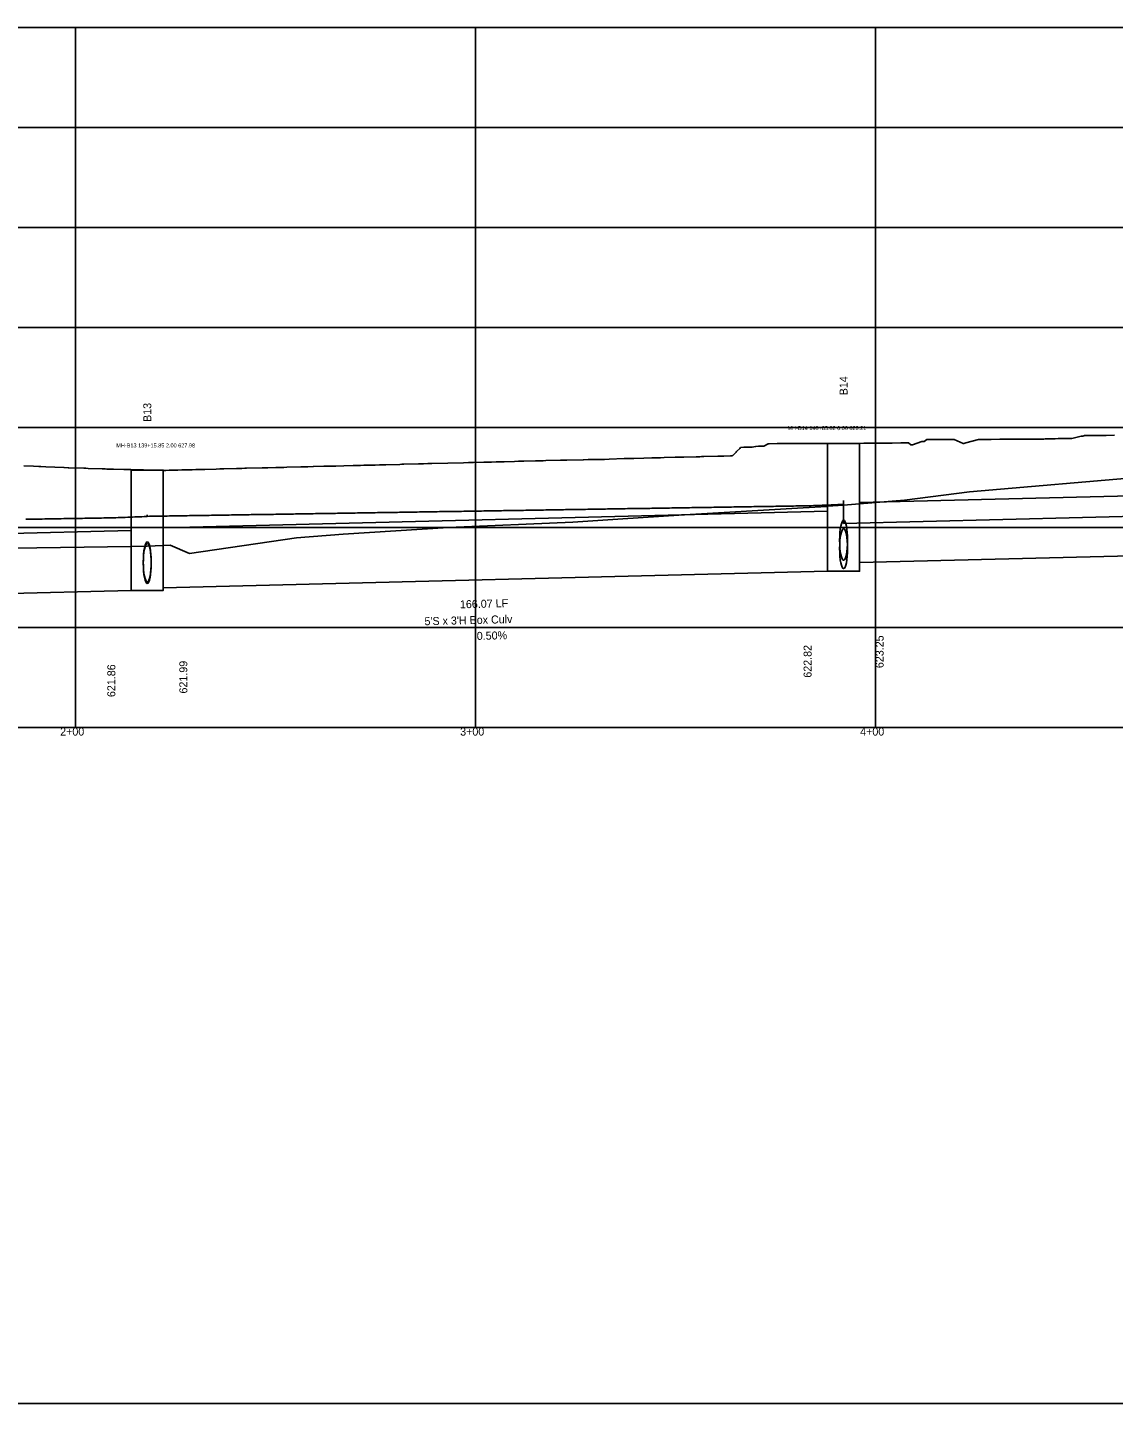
# Model space of a CAD drawing. Extents: x 2253035 to 2279930, y 13774972 to 13793443.
# Drawn here: x 2260149.5 to 2260421, y 13791972.5 to 13792316.4 of the extents above; entities that cross this region are included whole.
import ezdxf

# ---------------------------------------------------------------- set-up
doc = ezdxf.new("R2010")
doc.units = 0
for name, color, linetype in [('Default', 7, 'Continuous'), ('E_Utility_ATT_HH', 7, 'Continuous'), ('E_Utility_ATT_PR_PVC', 7, 'Continuous'), ('E_Utility_Telephone_Telephone Pedestal_TPED_Description', 7, 'Continuous'), ('E_Utillity_Water_Water Line_12in', 7, 'Continuous'), ('E_Utillity_Water_Water Line_1in', 7, 'Continuous'), ('E_Utillity_Water_Water Line_4in', 7, 'Continuous'), ('E_Utillity_Water_Water Line_8in', 7, 'Continuous')]:
    doc.layers.add(name, color=color, linetype=linetype)

msp = doc.modelspace()

# ---------------------------------------------------------------- linework, layer by layer
at = {"layer": 'Default'}
for p, q in [((2260161.48, 13792141.44), (2260161.48, 13792316.44)), ((2260261.48, 13792141.44), (2260261.48, 13792316.44)), ((2260361.48, 13792141.44), (2260361.48, 13792316.44)), ((2259961.48, 13792291.44), (2261350.66, 13792291.44)), ((2259961.48, 13792266.44), (2261350.66, 13792266.44)), ((2259961.48, 13792241.44), (2261350.66, 13792241.44)), ((2259961.48, 13792216.44), (2261350.66, 13792216.44)), ((2259961.48, 13792191.44), (2261350.66, 13792191.44)), ((2259961.48, 13792166.44), (2261350.66, 13792166.44)), ((2258357.4, 13791972.48), (2265626.63, 13791972.48))]:
    msp.add_line(p, q, dxfattribs=at)
msp.add_lwpolyline([(2259961.48, 13792141.44), (2259961.48, 13792316.44), (2261350.66, 13792316.44), (2261350.66, 13792141.44)], close=True, dxfattribs=at)
at = {"layer": 'E_Utility_ATT_PR_PVC'}
for p, q in [((2260353.54, 13792198.25), (2260353.54, 13792192.44)), ((2260179.47, 13792194.65), (2260179.47, 13792194.25))]:
    msp.add_line(p, q, dxfattribs=at)
for points in [[(2260179.47, 13792194.25), (2260180.02, 13792194.26), (2260180.57, 13792194.27), (2260181.13, 13792194.28), (2260181.68, 13792194.29), (2260182.23, 13792194.29), (2260182.79, 13792194.3), (2260183.34, 13792194.31), (2260183.89, 13792194.32), (2260184.45, 13792194.33), (2260185, 13792194.34), (2260185.55, 13792194.35), (2260186.11, 13792194.36), (2260186.66, 13792194.36), (2260187.21, 13792194.37), (2260187.77, 13792194.38), (2260188.32, 13792194.39), (2260188.87, 13792194.4), (2260189.43, 13792194.41), (2260189.98, 13792194.42), (2260190.53, 13792194.43), (2260191.08, 13792194.44), (2260191.64, 13792194.44), (2260192.19, 13792194.45), (2260192.74, 13792194.46), (2260193.3, 13792194.47), (2260193.85, 13792194.48), (2260194.4, 13792194.49), (2260194.96, 13792194.5), (2260195.51, 13792194.51), (2260196.06, 13792194.51), (2260196.62, 13792194.52), (2260197.17, 13792194.53), (2260197.72, 13792194.54), (2260198.28, 13792194.55), (2260198.83, 13792194.56), (2260199.38, 13792194.57), (2260199.94, 13792194.58), (2260200.49, 13792194.59), (2260201.04, 13792194.59), (2260201.6, 13792194.6), (2260202.15, 13792194.61), (2260202.7, 13792194.62), (2260203.26, 13792194.63), (2260203.81, 13792194.64), (2260204.36, 13792194.65), (2260204.92, 13792194.66), (2260205.47, 13792194.67), (2260206.02, 13792194.67), (2260206.58, 13792194.68), (2260207.13, 13792194.69), (2260207.68, 13792194.7), (2260208.24, 13792194.71), (2260208.79, 13792194.72), (2260209.34, 13792194.73), (2260209.9, 13792194.74), (2260210.45, 13792194.74), (2260211, 13792194.75), (2260211.56, 13792194.76), (2260212.11, 13792194.77), (2260212.66, 13792194.78), (2260213.22, 13792194.79), (2260213.77, 13792194.8), (2260214.32, 13792194.81), (2260214.88, 13792194.82), (2260215.43, 13792194.82), (2260215.98, 13792194.83), (2260216.54, 13792194.84), (2260217.09, 13792194.85), (2260217.64, 13792194.86), (2260218.2, 13792194.87), (2260218.75, 13792194.88), (2260219.3, 13792194.89), (2260219.86, 13792194.89), (2260220.41, 13792194.9), (2260220.96, 13792194.91), (2260221.51, 13792194.92), (2260222.07, 13792194.93), (2260222.62, 13792194.94), (2260223.17, 13792194.95), (2260223.73, 13792194.96), (2260224.28, 13792194.97), (2260224.83, 13792194.97), (2260225.39, 13792194.98), (2260225.94, 13792194.99), (2260226.49, 13792195), (2260227.05, 13792195.01), (2260227.6, 13792195.02), (2260228.15, 13792195.03), (2260228.71, 13792195.04), (2260229.26, 13792195.04), (2260229.81, 13792195.05), (2260230.37, 13792195.06), (2260230.92, 13792195.07), (2260231.47, 13792195.08), (2260232.03, 13792195.09), (2260232.58, 13792195.1), (2260233.13, 13792195.11), (2260233.69, 13792195.12), (2260234.24, 13792195.12), (2260234.79, 13792195.13), (2260235.35, 13792195.14), (2260235.9, 13792195.15), (2260236.45, 13792195.16), (2260237.01, 13792195.17), (2260237.56, 13792195.18), (2260238.11, 13792195.19), (2260238.67, 13792195.19), (2260239.22, 13792195.2), (2260239.77, 13792195.21), (2260240.33, 13792195.22), (2260240.88, 13792195.23), (2260241.43, 13792195.24), (2260241.99, 13792195.25), (2260242.54, 13792195.26), (2260243.09, 13792195.27), (2260243.65, 13792195.27), (2260244.2, 13792195.28), (2260244.75, 13792195.29), (2260245.31, 13792195.3), (2260245.86, 13792195.31), (2260246.41, 13792195.32), (2260246.97, 13792195.33), (2260247.52, 13792195.34), (2260248.07, 13792195.35), (2260248.63, 13792195.35), (2260249.18, 13792195.36), (2260249.73, 13792195.37), (2260250.29, 13792195.38), (2260250.84, 13792195.39), (2260251.39, 13792195.4), (2260251.94, 13792195.41), (2260252.5, 13792195.42), (2260253.05, 13792195.42), (2260253.6, 13792195.43), (2260254.16, 13792195.44), (2260254.71, 13792195.45), (2260255.26, 13792195.46), (2260255.82, 13792195.47), (2260256.37, 13792195.48), (2260256.92, 13792195.49), (2260257.48, 13792195.5), (2260258.03, 13792195.5), (2260258.58, 13792195.51), (2260259.14, 13792195.52), (2260259.69, 13792195.53), (2260260.24, 13792195.54), (2260260.8, 13792195.55), (2260261.35, 13792195.56), (2260261.9, 13792195.57), (2260262.46, 13792195.57), (2260263.01, 13792195.58), (2260263.56, 13792195.59), (2260264.12, 13792195.6), (2260264.67, 13792195.61), (2260265.22, 13792195.62), (2260265.78, 13792195.63), (2260266.33, 13792195.64), (2260266.88, 13792195.65), (2260267.44, 13792195.65), (2260267.99, 13792195.66), (2260268.54, 13792195.67), (2260269.1, 13792195.68), (2260269.65, 13792195.69), (2260270.2, 13792195.7), (2260270.76, 13792195.71), (2260271.31, 13792195.72), (2260271.86, 13792195.72), (2260272.42, 13792195.73), (2260272.97, 13792195.74), (2260273.52, 13792195.75), (2260274.08, 13792195.76), (2260274.63, 13792195.77), (2260275.18, 13792195.78), (2260275.74, 13792195.79), (2260276.29, 13792195.8), (2260276.84, 13792195.8), (2260277.4, 13792195.81), (2260277.95, 13792195.82), (2260278.5, 13792195.83), (2260279.06, 13792195.84), (2260279.61, 13792195.85), (2260280.16, 13792195.86), (2260280.72, 13792195.87), (2260281.27, 13792195.87), (2260281.82, 13792195.88), (2260282.37, 13792195.89), (2260282.93, 13792195.9), (2260283.48, 13792195.91), (2260284.03, 13792195.92), (2260284.59, 13792195.93), (2260285.14, 13792195.94), (2260285.69, 13792195.95), (2260286.25, 13792195.95), (2260286.8, 13792195.96), (2260287.35, 13792195.97), (2260287.91, 13792195.98), (2260288.46, 13792195.99), (2260289.01, 13792196), (2260289.57, 13792196.01), (2260290.12, 13792196.02), (2260290.67, 13792196.03), (2260291.23, 13792196.03), (2260291.78, 13792196.04), (2260292.33, 13792196.05), (2260292.89, 13792196.06), (2260293.44, 13792196.07), (2260293.99, 13792196.08), (2260294.55, 13792196.09), (2260295.1, 13792196.1), (2260295.65, 13792196.1), (2260296.21, 13792196.11), (2260296.76, 13792196.12), (2260297.31, 13792196.13), (2260297.87, 13792196.14), (2260298.42, 13792196.15), (2260298.97, 13792196.16), (2260299.53, 13792196.17), (2260300.08, 13792196.18), (2260300.63, 13792196.18), (2260301.19, 13792196.19), (2260301.74, 13792196.2), (2260302.29, 13792196.21), (2260302.85, 13792196.22), (2260303.4, 13792196.23), (2260303.95, 13792196.24), (2260304.51, 13792196.25), (2260305.06, 13792196.25), (2260305.61, 13792196.26), (2260306.17, 13792196.27), (2260306.72, 13792196.28), (2260307.27, 13792196.29), (2260307.83, 13792196.3), (2260308.38, 13792196.31), (2260308.93, 13792196.32), (2260309.49, 13792196.33), (2260310.04, 13792196.33), (2260310.59, 13792196.34), (2260311.15, 13792196.35), (2260311.7, 13792196.36), (2260312.25, 13792196.37), (2260312.8, 13792196.38), (2260313.36, 13792196.39), (2260313.91, 13792196.4), (2260314.46, 13792196.4), (2260315.02, 13792196.41), (2260315.57, 13792196.42), (2260316.12, 13792196.43), (2260316.68, 13792196.44), (2260317.23, 13792196.45), (2260317.78, 13792196.46), (2260318.34, 13792196.47), (2260318.89, 13792196.48), (2260319.44, 13792196.48), (2260320, 13792196.49), (2260320.55, 13792196.5), (2260321.1, 13792196.51), (2260321.66, 13792196.52), (2260322.21, 13792196.53), (2260322.76, 13792196.54), (2260323.32, 13792196.55), (2260323.87, 13792196.56), (2260324.42, 13792196.56), (2260324.98, 13792196.57), (2260325.53, 13792196.58), (2260326.08, 13792196.59), (2260326.64, 13792196.6), (2260327.19, 13792196.61), (2260327.74, 13792196.62), (2260328.3, 13792196.63), (2260328.85, 13792196.63), (2260329.4, 13792196.64), (2260329.96, 13792196.65), (2260330.51, 13792196.66), (2260331.06, 13792196.67), (2260331.62, 13792196.68), (2260332.17, 13792196.69), (2260332.72, 13792196.7), (2260333.28, 13792196.71), (2260333.83, 13792196.71), (2260334.38, 13792196.72), (2260334.94, 13792196.73), (2260335.49, 13792196.74), (2260336.04, 13792196.75), (2260336.6, 13792196.76), (2260337.15, 13792196.77), (2260337.7, 13792196.78), (2260338.26, 13792196.78), (2260338.81, 13792196.79), (2260339.36, 13792196.8), (2260339.92, 13792196.81), (2260340.47, 13792196.82), (2260341.02, 13792196.83), (2260341.58, 13792196.84), (2260342.13, 13792196.85), (2260342.68, 13792196.86), (2260343.23, 13792196.86), (2260343.79, 13792196.87), (2260344.34, 13792196.88), (2260344.89, 13792196.89), (2260345.45, 13792196.9), (2260346, 13792196.92), (2260346.55, 13792196.94), (2260347.11, 13792196.97), (2260347.66, 13792196.99), (2260348.21, 13792197.01), (2260348.77, 13792197.03), (2260349.32, 13792197.06), (2260349.87, 13792197.08), (2260350.43, 13792197.1), (2260350.98, 13792197.12), (2260351.53, 13792197.15), (2260352.09, 13792197.17), (2260352.64, 13792197.19), (2260353.19, 13792197.21), (2260353.54, 13792197.23), (2260353.54, 13792198.25)], [(2260353.54, 13792192.44), (2260512.87, 13792196.42)], [(2260149.07, 13792193.52), (2260149.66, 13792193.53), (2260150.26, 13792193.54), (2260150.85, 13792193.54), (2260151.44, 13792193.55), (2260152.04, 13792193.56), (2260152.63, 13792193.57), (2260153.22, 13792193.58), (2260153.81, 13792193.59), (2260154.41, 13792193.6), (2260155, 13792193.61), (2260155.59, 13792193.62), (2260156.19, 13792193.63), (2260156.78, 13792193.64), (2260157.37, 13792193.65), (2260157.96, 13792193.66), (2260158.56, 13792193.67), (2260159.15, 13792193.68), (2260159.74, 13792193.69), (2260160.34, 13792193.7), (2260160.93, 13792193.71), (2260161.52, 13792193.72), (2260162.11, 13792193.73), (2260162.71, 13792193.74), (2260163.3, 13792193.75), (2260163.89, 13792193.76), (2260164.49, 13792193.77), (2260165.08, 13792193.78), (2260165.67, 13792193.79), (2260166.27, 13792193.8), (2260166.86, 13792193.81), (2260167.45, 13792193.82), (2260168.04, 13792193.83), (2260168.64, 13792193.84), (2260169.23, 13792193.85), (2260169.82, 13792193.86), (2260170.42, 13792193.87), (2260171.01, 13792193.88), (2260171.6, 13792193.89), (2260172.19, 13792193.92), (2260172.79, 13792193.94), (2260173.38, 13792193.97), (2260173.97, 13792193.99), (2260174.57, 13792194.02), (2260175.16, 13792194.04), (2260175.75, 13792194.06), (2260176.34, 13792194.09), (2260176.94, 13792194.11), (2260177.53, 13792194.14), (2260178.12, 13792194.16), (2260178.72, 13792194.19), (2260179.31, 13792194.21), (2260179.47, 13792194.22), (2260179.47, 13792194.65)]]:
    msp.add_lwpolyline(points, dxfattribs=at)
at = {"layer": 'E_Utillity_Water_Water Line_12in'}
for points in [[(2260349.54, 13792212.48), (2260357.54, 13792212.48), (2260357.54, 13792180.54), (2260349.54, 13792180.54)], [(2260175.47, 13792205.82), (2260183.47, 13792205.82), (2260183.47, 13792175.74), (2260175.47, 13792175.74)]]:
    msp.add_lwpolyline(points, close=True, dxfattribs=at)
at = {"layer": 'E_Utillity_Water_Water Line_1in'}
msp.add_lwpolyline([(2260110.5, 13792185.8), (2260175.47, 13792186.67), (2260175.47, 13792186.67), (2260179.47, 13792186.81), (2260179.47, 13792186.81), (2260183.47, 13792186.95), (2260183.47, 13792186.95), (2260185.21, 13792187.03), (2260189.98, 13792184.98), (2260216.8, 13792188.91), (2260228.42, 13792189.81), (2260254.77, 13792191.45), (2260285.88, 13792192.78), (2260298.34, 13792193.59), (2260312.33, 13792194.53), (2260343.44, 13792196.36), (2260349.38, 13792196.75), (2260349.54, 13792196.76), (2260349.54, 13792196.76), (2260353.54, 13792197.08), (2260353.54, 13792197.08), (2260357.54, 13792197.4), (2260357.54, 13792197.4), (2260368.74, 13792198.32), (2260385.04, 13792200.38), (2260429.58, 13792204.18)], dxfattribs=at)
at = {"layer": 'E_Utillity_Water_Water Line_4in'}
for p, q in [((2260357.54, 13792197.69), (2260559.63, 13792202.74)), ((2260183.47, 13792191.39), (2260349.54, 13792195.54)), ((2260013.74, 13792186.7), (2260175.47, 13792190.74)), ((2260357.54, 13792182.69), (2260559.63, 13792187.74)), ((2260183.47, 13792176.39), (2260349.54, 13792180.54)), ((2260013.74, 13792171.7), (2260175.47, 13792175.74))]:
    msp.add_line(p, q, dxfattribs=at)
for centre in [(2260353.54, 13792188.27), (2260353.54, 13792186.18), (2260179.47, 13792182.87), (2260179.47, 13792182.47)]:
    msp.add_ellipse(centre, major_axis=(0, 5), ratio=0.2, dxfattribs=at)
at = {"layer": 'E_Utillity_Water_Water Line_8in'}
msp.add_lwpolyline([(2260148.61, 13792206.85), (2260151.04, 13792206.75), (2260152.35, 13792206.7), (2260152.83, 13792206.68), (2260154.07, 13792206.63), (2260158.56, 13792206.45), (2260158.72, 13792206.44), (2260159.71, 13792206.41), (2260159.81, 13792206.4), (2260163.61, 13792206.27), (2260164.13, 13792206.25), (2260164.66, 13792206.23), (2260168.2, 13792206.12), (2260168.94, 13792206.1), (2260169.37, 13792206.08), (2260169.75, 13792206.07), (2260170.98, 13792206.04), (2260173.62, 13792205.96), (2260175.26, 13792205.92), (2260175.47, 13792205.91), (2260175.47, 13792205.91), (2260176.38, 13792205.89), (2260178.54, 13792205.84), (2260179.47, 13792205.82), (2260179.47, 13792205.82), (2260179.63, 13792205.82), (2260179.71, 13792205.81), (2260179.77, 13792205.81), (2260182.08, 13792205.76), (2260183.47, 13792205.73), (2260183.47, 13792205.73), (2260183.62, 13792205.73), (2260184.1, 13792205.74), (2260184.11, 13792205.74), (2260184.12, 13792205.74), (2260184.9, 13792205.76), (2260185.73, 13792205.78), (2260186.12, 13792205.79), (2260186.13, 13792205.79), (2260186.68, 13792205.81), (2260186.98, 13792205.81), (2260187.04, 13792205.82), (2260187.04, 13792205.82), (2260187.09, 13792205.82), (2260188.1, 13792205.84), (2260188.27, 13792205.85), (2260189.54, 13792205.88), (2260189.85, 13792205.89), (2260189.91, 13792205.89), (2260189.95, 13792205.89), (2260190.59, 13792205.91), (2260190.66, 13792205.91), (2260191.63, 13792205.93), (2260192.64, 13792205.96), (2260192.87, 13792205.96), (2260193.27, 13792205.97), (2260193.85, 13792205.99), (2260196.72, 13792206.06), (2260197.58, 13792206.09), (2260198.62, 13792206.11), (2260201.78, 13792206.19), (2260202.48, 13792206.21), (2260203.11, 13792206.23), (2260203.83, 13792206.25), (2260204.3, 13792206.26), (2260208.18, 13792206.36), (2260208.42, 13792206.36), (2260209.48, 13792206.39), (2260209.62, 13792206.39), (2260211.57, 13792206.44), (2260213.58, 13792206.44), (2260213.62, 13792206.44), (2260214.31, 13792206.51), (2260217.83, 13792206.6), (2260218.95, 13792206.63), (2260218.95, 13792206.63), (2260218.96, 13792206.63), (2260219.44, 13792206.64), (2260219.63, 13792206.65), (2260220.91, 13792206.68), (2260220.94, 13792206.68), (2260220.94, 13792206.68), (2260223.62, 13792206.75), (2260225.39, 13792206.8), (2260226.58, 13792206.83), (2260228.62, 13792206.88), (2260230.9, 13792206.94), (2260232.51, 13792206.98), (2260232.73, 13792206.98), (2260233.62, 13792207.01), (2260236.43, 13792207.08), (2260237.51, 13792207.11), (2260237.92, 13792207.12), (2260238.38, 13792207.13), (2260239.06, 13792207.15), (2260242.59, 13792207.24), (2260243.1, 13792207.25), (2260243.62, 13792207.26), (2260247.3, 13792207.36), (2260247.52, 13792207.36), (2260248.48, 13792207.39), (2260249.58, 13792207.42), (2260249.65, 13792207.42), (2260250.63, 13792207.44), (2260254.63, 13792207.55), (2260258.52, 13792207.65), (2260259.76, 13792207.68), (2260261, 13792207.71), (2260261.03, 13792207.71), (2260261.03, 13792207.71), (2260263.62, 13792207.78), (2260265.52, 13792207.82), (2260266.66, 13792207.85), (2260266.76, 13792207.86), (2260268.72, 13792207.91), (2260271.26, 13792207.97), (2260272.23, 13792208), (2260273.62, 13792208.03), (2260276.55, 13792208.11), (2260277.55, 13792208.13), (2260277.98, 13792208.14), (2260278.46, 13792208.16), (2260279.08, 13792208.17), (2260282.73, 13792208.26), (2260283.17, 13792208.28), (2260283.94, 13792208.3), (2260284.35, 13792208.31), (2260288.46, 13792208.41), (2260288.55, 13792208.41), (2260289.67, 13792208.44), (2260289.67, 13792208.44), (2260289.7, 13792208.44), (2260293.39, 13792208.44), (2260293.78, 13792208.44), (2260294.95, 13792208.58), (2260298.7, 13792208.67), (2260299.9, 13792208.7), (2260301.09, 13792208.73), (2260301.12, 13792208.74), (2260303.62, 13792208.8), (2260305.57, 13792208.85), (2260307.58, 13792208.9), (2260307.67, 13792208.9), (2260307.78, 13792208.91), (2260308.72, 13792208.93), (2260311.4, 13792209), (2260312.31, 13792209.02), (2260313.62, 13792209.06), (2260316.67, 13792209.13), (2260317.59, 13792209.16), (2260318.03, 13792209.17), (2260318.62, 13792209.18), (2260322.12, 13792209.27), (2260322.59, 13792209.29), (2260323.29, 13792209.3), (2260323.6, 13792209.31), (2260325.26, 13792209.35), (2260325.65, 13792209.41), (2260325.77, 13792209.43), (2260325.82, 13792209.44), (2260326.65, 13792210.29), (2260326.71, 13792210.3), (2260326.8, 13792210.44), (2260327.58, 13792211.23), (2260327.79, 13792211.44), (2260327.84, 13792211.49), (2260328.62, 13792211.53), (2260330.62, 13792211.54), (2260331.58, 13792211.74), (2260332.27, 13792211.76), (2260332.64, 13792211.76), (2260333.38, 13792211.78), (2260333.51, 13792211.78), (2260333.62, 13792211.83), (2260334.72, 13792212.34), (2260334.8, 13792212.34), (2260334.83, 13792212.34), (2260334.9, 13792212.34), (2260334.97, 13792212.35), (2260336.94, 13792212.44), (2260338.44, 13792212.45), (2260338.66, 13792212.45), (2260340.86, 13792212.45), (2260340.9, 13792212.45), (2260343.2, 13792212.46), (2260343.71, 13792212.46), (2260345.76, 13792212.46), (2260347.87, 13792212.46), (2260348.66, 13792212.47), (2260349.54, 13792212.47), (2260349.54, 13792212.47), (2260349.54, 13792212.47), (2260352.03, 13792212.47), (2260352.13, 13792212.48), (2260352.27, 13792212.48), (2260353.54, 13792212.48), (2260353.54, 13792212.48), (2260353.62, 13792212.48), (2260353.65, 13792212.48), (2260354.84, 13792212.48), (2260355.02, 13792212.49), (2260357.54, 13792212.49), (2260357.54, 13792212.49), (2260357.6, 13792212.49), (2260358.62, 13792212.5), (2260360.1, 13792212.5), (2260360.26, 13792212.51), (2260362.62, 13792212.52), (2260362.79, 13792212.53), (2260362.94, 13792212.53), (2260363.62, 13792212.53), (2260365.33, 13792212.54), (2260365.72, 13792212.58), (2260367.88, 13792212.59), (2260368.13, 13792212.62), (2260368.28, 13792212.62), (2260368.62, 13792212.62), (2260368.84, 13792212.66), (2260369.79, 13792212.66), (2260370.34, 13792212.11), (2260370.74, 13792212.12), (2260373.07, 13792212.97), (2260373.25, 13792212.98), (2260373.62, 13792212.99), (2260373.65, 13792212.99), (2260374.35, 13792213.44), (2260374.84, 13792213.44), (2260374.85, 13792213.44), (2260378.35, 13792213.44), (2260378.4, 13792213.44), (2260378.62, 13792213.44), (2260378.86, 13792213.44), (2260378.87, 13792213.44), (2260381.15, 13792213.44), (2260383.44, 13792212.48), (2260383.54, 13792212.48), (2260383.62, 13792212.48), (2260384.1, 13792212.59), (2260387.3, 13792213.48), (2260388.69, 13792213.49), (2260390.2, 13792213.49), (2260390.35, 13792213.49), (2260390.47, 13792213.49), (2260392.56, 13792213.5), (2260392.59, 13792213.5), (2260393.62, 13792213.5), (2260393.67, 13792213.5), (2260394.87, 13792213.51), (2260397.05, 13792213.51), (2260397.36, 13792213.53), (2260398.62, 13792213.53), (2260398.84, 13792213.54), (2260400.24, 13792213.55), (2260402.47, 13792213.55), (2260402.81, 13792213.58), (2260402.98, 13792213.58), (2260403.62, 13792213.58), (2260403.94, 13792213.61), (2260404.62, 13792213.61), (2260406.45, 13792213.62), (2260407.16, 13792213.7), (2260408.62, 13792213.71), (2260408.89, 13792213.71), (2260410.61, 13792213.72), (2260412.94, 13792214.26), (2260413.06, 13792214.26), (2260413.13, 13792214.26), (2260413.35, 13792214.26), (2260413.36, 13792214.26), (2260413.62, 13792214.38), (2260413.76, 13792214.44), (2260415.55, 13792214.49), (2260419.22, 13792214.49), (2260421.3, 13792214.5)], dxfattribs=at)

# ---------------------------------------------------------------- texts
at = {"layer": 'Default'}
for s, p in [('2+00', (2260157.68, 13792139.44)), ('3+00', (2260257.68, 13792139.44)), ('4+00', (2260357.68, 13792139.44))]:
    msp.add_text(s, height=2, dxfattribs=at).set_placement(p)
at = {"layer": 'E_Utility_ATT_HH'}
for s, rotation, p in [('B14', 90, (2260354.54, 13792224.51)), ('B13', 90, (2260180.47, 13792217.84)), ('166.07 LF', 1.4321, (2260257.65, 13792171.25)), ("5'S x 3'H Box Culv", 1.4321, (2260248.79, 13792167.02)), ('0.50%', 1.4321, (2260261.86, 13792163.35)), ('623.25', 90, (2260363.54, 13792156.31)), ('622.82', 90, (2260345.54, 13792153.91)), ('621.99', 90, (2260189.47, 13792149.96)), ('621.86', 90, (2260171.47, 13792149.07))]:
    msp.add_text(s, height=2, rotation=rotation, dxfattribs=at).set_placement(p)
at = {"layer": 'E_Utility_Telephone_Telephone Pedestal_TPED_Description'}
for s, p in [('MH-B14 140+85.02 6.00 629.21', (2260339.53, 13792215.8)), ('MH-B13 139+15.85 2.00 627.98', (2260171.72, 13792211.47))]:
    msp.add_text(s, height=1, rotation=0, dxfattribs=at).set_placement(p)

doc.saveas('drawing.dxf')
